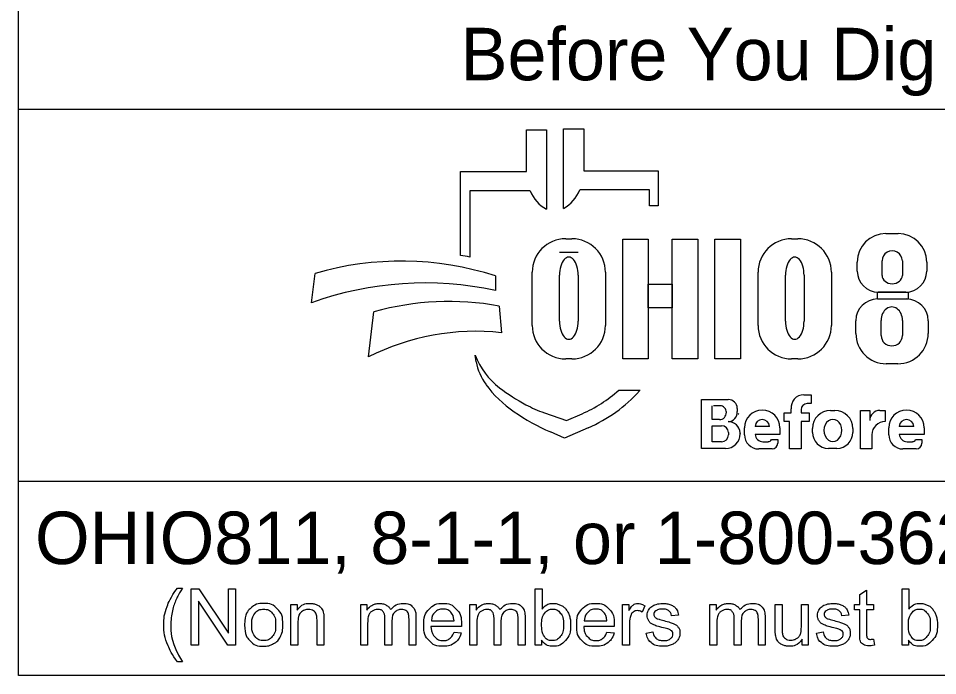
# Model space of a CAD drawing. Extents: x 0 to 34, y 0 to 22.
# Drawn here: x 2.978 to 5.431, y 2.143 to 3.897 of the extents above; entities that cross this region are included whole.
import ezdxf

# ---------------------------------------------------------------- set-up
doc = ezdxf.new("R2010")
doc.units = 0
doc.layers.add('GM_X_Adjacent_County', color=7, linetype='Continuous')
doc.layers.add('GM_X_Township', color=7, linetype='Continuous')

msp = doc.modelspace()

# ---------------------------------------------------------------- linework, layer by layer
at = {"layer": 'GM_X_Adjacent_County'}
for p, q in [((4.3335, 3.4883), (4.3335, 3.5998)), ((4.3335, 3.5998), (4.3872, 3.5998)), ((4.3872, 3.5998), (4.3872, 3.3877)), ((4.4329, 3.39), (4.4329, 3.6021)), ((4.4329, 3.6021), (4.4865, 3.6021)), ((4.4865, 3.6021), (4.4865, 3.4906)), ((4.1576, 3.2644), (4.1576, 3.4883)), ((4.1576, 3.4883), (4.3335, 3.4883)), ((4.4865, 3.4906), (4.6857, 3.4906)), ((4.6857, 3.4906), (4.6857, 3.3968)), ((4.1828, 3.4369), (4.1828, 3.26)), ((4.3439, 3.4369), (4.1828, 3.4369)), ((4.6625, 3.4392), (4.4761, 3.4392)), ((4.6625, 3.3968), (4.6625, 3.4392)), ((4.6857, 3.3968), (4.6625, 3.3968)), ((5.2931, 3.3231), (5.3258, 3.3231)), ((4.4385, 3.3091), (4.4551, 3.3091)), ((5.0416, 3.3091), (5.0581, 3.3091)), ((4.4718, 3.2721), (4.422, 3.2721)), ((5.2168, 3.2225), (5.2168, 3.2468)), ((5.283, 3.2111), (5.283, 3.2504)), ((5.3371, 3.2504), (5.3371, 3.2111)), ((5.4022, 3.2468), (5.4022, 3.2225)), ((3.7602, 3.1381), (3.7696, 3.2162)), ((4.3491, 3.0776), (4.3491, 3.2196)), ((4.5445, 3.2196), (4.5445, 3.0776)), ((4.9521, 3.0776), (4.9521, 3.2196)), ((5.1476, 3.2196), (5.1476, 3.0776)), ((4.2509, 3.2097), (4.2509, 3.1709)), ((4.422, 3.089), (4.422, 3.2114)), ((4.4718, 3.2114), (4.4718, 3.089)), ((5.025, 3.089), (5.025, 3.2114)), ((5.0748, 3.2114), (5.0748, 3.089)), ((5.3462, 3.1665), (5.2728, 3.1665)), ((5.271, 3.1482), (5.3483, 3.1482)), ((4.2608, 3.1291), (4.2671, 3.0582)), ((3.912, 2.9936), (3.9267, 3.1137)), ((5.2131, 3.0563), (5.2131, 3.0903)), ((5.2806, 3.0503), (5.2806, 3.0912)), ((5.3374, 3.0912), (5.3374, 3.0503)), ((5.4062, 3.0903), (5.4062, 3.0563)), ((4.1997, 2.9807), (4.1967, 2.9986)), ((4.4551, 2.9882), (4.4385, 2.9882)), ((5.0581, 2.9882), (5.0416, 2.9882)), ((5.3252, 2.9753), (5.2941, 2.9753)), ((4.58, 2.9048), (4.6375, 2.9048)), ((4.8013, 2.749), (4.8013, 2.8798)), ((4.8013, 2.8798), (4.8725, 2.8798)), ((5.0739, 2.8926), (5.0934, 2.8926)), ((5.0934, 2.8926), (5.0934, 2.8696)), ((4.8293, 2.8263), (4.8293, 2.8632)), ((4.8545, 2.8632), (4.8332, 2.8632)), ((4.8963, 2.856), (4.8963, 2.8481)), ((5.0406, 2.8442), (5.0406, 2.8546)), ((5.0667, 2.8526), (5.0667, 2.8442)), ((5.0934, 2.8691), (5.0832, 2.8691)), ((5.1451, 2.8508), (5.1573, 2.8508)), ((5.2254, 2.7478), (5.2254, 2.8505)), ((5.2254, 2.8505), (5.2499, 2.8505)), ((5.2499, 2.8505), (5.2499, 2.8237)), ((5.2772, 2.8505), (5.291, 2.8505)), ((5.291, 2.8505), (5.291, 2.8209)), ((4.3816, 2.8444), (4.441, 2.8239)), ((4.441, 2.8239), (4.4821, 2.8417)), ((4.8487, 2.8263), (4.8293, 2.8263)), ((5.0213, 2.8212), (5.0213, 2.8442)), ((5.0213, 2.8442), (5.0406, 2.8442)), ((5.0667, 2.8442), (5.0883, 2.8442)), ((5.0883, 2.8442), (5.0883, 2.8212)), ((4.4983, 2.8044), (4.435, 2.7769)), ((4.8293, 2.7669), (4.8293, 2.8097)), ((4.8293, 2.8097), (4.8548, 2.8097)), ((4.9159, 2.7858), (4.9159, 2.8042)), ((4.9824, 2.8082), (4.9439, 2.8082)), ((5.0104, 2.8042), (5.0104, 2.7866)), ((5.0362, 2.8212), (5.0213, 2.8212)), ((5.0362, 2.7478), (5.0362, 2.8212)), ((5.0883, 2.8212), (5.0667, 2.8212)), ((5.0667, 2.8212), (5.0667, 2.7478)), ((5.0973, 2.7922), (5.0973, 2.8029)), ((5.2051, 2.8029), (5.2051, 2.7922)), ((5.3008, 2.7858), (5.3008, 2.8042)), ((5.3674, 2.8082), (5.3288, 2.8082)), ((5.3953, 2.8042), (5.3953, 2.7866)), ((4.435, 2.7769), (4.3976, 2.7934)), ((4.8729, 2.7916), (4.8729, 2.7853)), ((4.9043, 2.7887), (4.9043, 2.7884)), ((5.0104, 2.7866), (4.944, 2.7866)), ((4.9876, 2.7729), (5.0045, 2.7729)), ((5.0045, 2.7729), (5.0045, 2.7631)), ((5.2559, 2.786), (5.2559, 2.7478)), ((5.3953, 2.7866), (5.3289, 2.7866)), ((5.3725, 2.7729), (5.3894, 2.7729)), ((5.3894, 2.7729), (5.3894, 2.7631)), ((4.865, 2.749), (4.8013, 2.749)), ((4.8546, 2.7669), (4.8293, 2.7669)), ((4.9649, 2.7673), (4.979, 2.7673)), ((5.1623, 2.7494), (5.1401, 2.7494)), ((5.3498, 2.7673), (5.3639, 2.7673)), ((4.9892, 2.7478), (4.9538, 2.7478)), ((5.0667, 2.7478), (5.0362, 2.7478)), ((5.2559, 2.7478), (5.2254, 2.7478)), ((5.3742, 2.7478), (5.3388, 2.7478))]:
    msp.add_line(p, q, dxfattribs=at)
for points in [[(4.591, 3.3081), (4.6589, 3.3081), (4.6589, 2.9881), (4.591, 2.9881)], [(4.7231, 3.3081), (4.7911, 3.3081), (4.7911, 2.9881), (4.7231, 2.9881)], [(4.8364, 3.3081), (4.9052, 3.3081), (4.9052, 2.9881), (4.8364, 2.9881)], [(4.6589, 3.1882), (4.7231, 3.1882), (4.7231, 3.1242), (4.6589, 3.1242)], [(5.2706, 3.1665), (5.3523, 3.1665), (5.3523, 3.1481), (5.2706, 3.1481)]]:
    msp.add_lwpolyline(points, close=True, dxfattribs=at)
for points in [[(3.4021, 2.3766), (3.4153, 2.3766)], [(3.4389, 2.2239), (3.4389, 2.3741), (3.4592, 2.3741), (3.5382, 2.2561), (3.5382, 2.3741), (3.5572, 2.3741), (3.5572, 2.2239), (3.5369, 2.2239), (3.4579, 2.3419), (3.4579, 2.2239), (3.4389, 2.2239)], [(4.3743, 2.2239), (4.3573, 2.2239), (4.3573, 2.3741), (4.3757, 2.3741), (4.3757, 2.3206)], [(5.2233, 2.2558), (5.2233, 2.3185), (5.2097, 2.3185), (5.2097, 2.3328), (5.2233, 2.3328), (5.2233, 2.3597), (5.2417, 2.3708), (5.2417, 2.3328), (5.2601, 2.3328), (5.2601, 2.3185), (5.2417, 2.3185), (5.2417, 2.2547)], [(5.3534, 2.2239), (5.3363, 2.2239), (5.3363, 2.3741), (5.3548, 2.3741), (5.3548, 2.3206)], [(3.7048, 2.2239), (3.7048, 2.3328), (3.7214, 2.3328), (3.7214, 2.3173)], [(3.8912, 2.2239), (3.8912, 2.3328), (3.9077, 2.3328), (3.9077, 2.3174)], [(4.1826, 2.2239), (4.1826, 2.3328), (4.1991, 2.3328), (4.1991, 2.3174)], [(4.5904, 2.2239), (4.5904, 2.3328), (4.607, 2.3328), (4.607, 2.3163)], [(4.8236, 2.2239), (4.8236, 2.3328), (4.8401, 2.3328), (4.8401, 2.3174)], [(4.9979, 2.2654), (4.9979, 2.3328), (5.0164, 2.3328), (5.0164, 2.2724)], [(5.0676, 2.2745), (5.0676, 2.3328), (5.0861, 2.3328), (5.0861, 2.2239), (5.0696, 2.2239)], [(4.6495, 2.3293), (4.643, 2.3122)], [(3.7233, 2.2833), (3.7233, 2.2239), (3.7048, 2.2239)], [(3.7932, 2.2908), (3.7932, 2.2239), (3.7748, 2.2239), (3.7748, 2.2901)], [(3.9743, 2.2871), (3.9743, 2.2239), (3.9559, 2.2239), (3.9559, 2.2946)], [(4.0388, 2.2986), (4.0388, 2.2239), (4.0203, 2.2239), (4.0203, 2.2924)], [(4.0799, 2.2887), (4.1406, 2.2887)], [(4.2657, 2.2871), (4.2657, 2.2239), (4.2473, 2.2239), (4.2473, 2.2946)], [(4.3301, 2.2986), (4.3301, 2.2239), (4.3117, 2.2239), (4.3117, 2.2924)], [(4.4879, 2.2887), (4.5486, 2.2887)], [(4.7394, 2.3046), (4.7213, 2.3022)], [(4.9067, 2.2871), (4.9067, 2.2239), (4.8883, 2.2239), (4.8883, 2.2946)], [(4.9711, 2.2986), (4.9711, 2.2239), (4.9527, 2.2239), (4.9527, 2.2924)], [(5.194, 2.3046), (5.1759, 2.3022)], [(3.9097, 2.2803), (3.9097, 2.2239), (3.8912, 2.2239)], [(4.16, 2.2736), (4.0788, 2.2736)], [(4.1404, 2.2591), (4.1595, 2.2567)], [(4.201, 2.2803), (4.201, 2.2239), (4.1826, 2.2239)], [(4.568, 2.2736), (4.4868, 2.2736)], [(4.5484, 2.2591), (4.5675, 2.2567)], [(4.6088, 2.2809), (4.6088, 2.2239), (4.5904, 2.2239)], [(4.653, 2.2564), (4.6712, 2.2593)], [(4.842, 2.2803), (4.842, 2.2239), (4.8236, 2.2239)], [(5.1076, 2.2564), (5.1258, 2.2593)], [(4.3743, 2.2375), (4.3743, 2.2239)], [(5.0696, 2.2239), (5.0696, 2.24)], [(5.2601, 2.2404), (5.2628, 2.2241)], [(5.3534, 2.2375), (5.3534, 2.2239)], [(3.4153, 2.1798), (3.4021, 2.1798)]]:
    msp.add_lwpolyline(points, dxfattribs=at)
for centre, radius, start, end in [((4.4353, 3.4736), 0.0985, 201.9296, 240.7469), ((4.3847, 3.476), 0.0985, 299.2531, 338.0704), ((5.2931, 3.2468), 0.0763, 90, 180), ((5.3258, 3.2468), 0.0763, 0, 90), ((4.4385, 3.2196), 0.0895, 90, 180), ((4.4551, 3.2196), 0.0895, 0, 90), ((5.0416, 3.2196), 0.0895, 90, 180), ((5.0581, 3.2196), 0.0895, 0, 90), ((4.0295, 2.4554), 0.8191, 79.2074, 81.0007), ((3.9997, 2.4302), 0.8191, 72.1402, 106.3144), ((5.2728, 3.2225), 0.056, 180, 270), ((5.3462, 3.2225), 0.056, 270, 0), ((4.0628, 2.2991), 0.8919, 77.8238, 109.8274), ((4.1267, 2.4094), 0.7322, 79.44, 105.8467), ((5.271, 3.0903), 0.0579, 90, 180), ((5.3483, 3.0903), 0.0579, 0, 90), ((4.4385, 3.0776), 0.0895, 180, 270), ((4.4551, 3.0776), 0.0895, 270, 0), ((5.0416, 3.0776), 0.0895, 180, 270), ((5.0581, 3.0776), 0.0895, 270, 0), ((4.1987, 2.4262), 0.6357, 83.8248, 116.8021), ((5.2941, 3.0563), 0.081, 180, 270), ((5.3252, 3.0563), 0.081, 270, 0), ((4.3841, 3.0707), 0.2008, 201.0457, 232.5314), ((4.341, 3.0048), 0.1433, 189.6817, 216.0884), ((4.4747, 3.1022), 0.3088, 216.0884, 235.7167), ((4.5766, 3.3219), 0.5173, 232.5314, 241.794), ((4.3387, 3.1722), 0.3602, 293.4582, 312.0712), ((4.3387, 3.1722), 0.401, 293.4582, 317.8286), ((4.8725, 2.856), 0.0238, 0, 90), ((5.0739, 2.859), 0.0335, 90, 187.5187), ((4.6412, 3.3465), 0.6044, 235.7167, 246.2325), ((4.4914, 3.1631), 0.3371, 241.794, 250.9821), ((4.8505, 2.8463), 0.0169, 357.8325, 90), ((4.8721, 2.8453), 0.0243, 270, 6.6529), ((4.9631, 2.8042), 0.0473, 0, 180), ((5.0832, 2.8526), 0.0165, 90, 180), ((5.1451, 2.8029), 0.0478, 90, 180), ((5.1573, 2.8029), 0.0478, 0, 90), ((5.2768, 2.8237), 0.0269, 89.2449, 180), ((5.3481, 2.8042), 0.0473, 0, 180), ((4.8487, 2.845), 0.0187, 270, 2.0582), ((4.8827, 2.8438), 0.0175, 347.4023, 0), ((4.9632, 2.8072), 0.0193, 2.9632, 177.0368), ((5.3481, 2.8072), 0.0193, 2.9632, 177.0368), ((4.8548, 2.7916), 0.0181, 0, 90), ((4.8722, 2.7889), 0.0321, 4.0748, 90), ((5.2908, 2.786), 0.0349, 89.6033, 180), ((4.8546, 2.7853), 0.0184, 270, 0), ((4.865, 2.7884), 0.0393, 270, 0), ((4.8714, 2.7887), 0.033, 0, 11.7502), ((4.9538, 2.7858), 0.038, 180, 270), ((4.9649, 2.7883), 0.021, 184.827, 270), ((4.979, 2.7767), 0.00938, 270, 335.9979), ((5.1401, 2.7922), 0.0428, 180, 270), ((5.1623, 2.7922), 0.0428, 270, 0), ((5.3388, 2.7858), 0.038, 180, 270), ((5.3498, 2.7883), 0.021, 184.827, 270), ((5.3639, 2.7767), 0.00938, 270, 335.9979), ((4.9892, 2.7631), 0.0152, 270, 0), ((5.3742, 2.7631), 0.0152, 270, 0)]:
    msp.add_arc(centre, radius, start, end, dxfattribs=at)
for centre, major_axis, ratio, start_param, end_param in [((5.31, 3.2504), (0.0271, 0), 0.969373, 0, 3.141593), ((4.4469, 3.2114), (0, 0.0484), 0.514403, 4.712389, 7.853982), ((5.0499, 3.2114), (0, 0.0484), 0.514403, 4.712389, 7.853982), ((5.31, 3.2111), (0.0271, 0), 0.818453, 3.141593, 6.283185), ((5.309, 3.0912), (0, 0.0358), 0.794529, 4.712389, 7.853982), ((4.4469, 3.089), (0, 0.0484), 0.514403, 1.570796, 4.712389), ((5.0499, 3.089), (0, 0.0484), 0.514403, 1.570796, 4.712389), ((5.309, 3.0503), (0.0284, 0), 0.959837, 3.141593, 6.283185), ((5.1517, 2.7976), (0, 0.029), 0.832186, 4.712389, 7.853982), ((5.1517, 2.7976), (0, 0.0302), 0.797287, 1.570796, 4.712389)]:
    msp.add_ellipse(centre, major_axis=major_axis, ratio=ratio, start_param=start_param, end_param=end_param, dxfattribs=at)
for points in [[(3.4021, 2.1798), (3.3869, 2.199), (3.3763, 2.2248), (3.3657, 2.2506), (3.3657, 2.2783), (3.3657, 2.3026), (3.3736, 2.325), (3.3829, 2.3509), (3.4021, 2.3766)], [(3.4153, 2.3766), (3.4029, 2.3553), (3.3989, 2.3462), (3.3927, 2.332), (3.3891, 2.3167), (3.3847, 2.2975), (3.3847, 2.2782), (3.3847, 2.2289), (3.4153, 2.1798)], [(3.5814, 2.2783), (3.5814, 2.3085), (3.5981, 2.3231), (3.6122, 2.3352), (3.6323, 2.3352), (3.6547, 2.3352), (3.669, 2.3205), (3.6832, 2.3058), (3.6832, 2.2799), (3.6832, 2.2589), (3.6769, 2.2469), (3.6706, 2.2348), (3.6586, 2.2282), (3.6466, 2.2215), (3.6323, 2.2215), (3.6095, 2.2215), (3.5954, 2.2362), (3.5814, 2.2508), (3.5814, 2.2783)], [(3.7214, 2.3173), (3.7334, 2.3352), (3.756, 2.3352), (3.7659, 2.3352), (3.7741, 2.3316), (3.7823, 2.3281), (3.7864, 2.3224), (3.7905, 2.3166), (3.7922, 2.3087), (3.7932, 2.3036), (3.7932, 2.2908)], [(3.9077, 2.3174), (3.9128, 2.3254), (3.9214, 2.3303), (3.9299, 2.3352), (3.9407, 2.3352), (3.9528, 2.3352), (3.9606, 2.3301), (3.9683, 2.3251), (3.9715, 2.3161), (3.9844, 2.3352), (4.0051, 2.3352), (4.0213, 2.3352), (4.03, 2.3262), (4.0388, 2.3172), (4.0388, 2.2986)], [(4.1595, 2.2567), (4.155, 2.24), (4.1428, 2.2307), (4.1306, 2.2215), (4.1117, 2.2215), (4.0878, 2.2215), (4.0738, 2.2362), (4.0598, 2.2509), (4.0598, 2.2774), (4.0598, 2.3049), (4.074, 2.32), (4.0881, 2.3352), (4.1106, 2.3352), (4.1324, 2.3352), (4.1463, 2.3203), (4.1601, 2.3055), (4.1601, 2.2785), (4.1601, 2.2769), (4.16, 2.2736)], [(4.1991, 2.3174), (4.2042, 2.3254), (4.2127, 2.3303), (4.2212, 2.3352), (4.2321, 2.3352), (4.2442, 2.3352), (4.2519, 2.3301), (4.2597, 2.3251), (4.2628, 2.3161), (4.2758, 2.3352), (4.2965, 2.3352), (4.3127, 2.3352), (4.3214, 2.3262), (4.3301, 2.3172), (4.3301, 2.2986)], [(4.3757, 2.3206), (4.3874, 2.3352), (4.4055, 2.3352), (4.4155, 2.3352), (4.4245, 2.3311), (4.4335, 2.3271), (4.4392, 2.3198), (4.445, 2.3124), (4.4483, 2.3021), (4.4516, 2.2918), (4.4516, 2.28), (4.4516, 2.252), (4.4378, 2.2368), (4.4239, 2.2215), (4.4046, 2.2215), (4.3853, 2.2215), (4.3743, 2.2375)], [(4.5675, 2.2567), (4.563, 2.24), (4.5508, 2.2307), (4.5386, 2.2215), (4.5196, 2.2215), (4.4958, 2.2215), (4.4818, 2.2362), (4.4678, 2.2509), (4.4678, 2.2774), (4.4678, 2.3049), (4.482, 2.32), (4.4961, 2.3352), (4.5186, 2.3352), (4.5404, 2.3352), (4.5543, 2.3203), (4.5681, 2.3055), (4.5681, 2.2785), (4.5681, 2.2769), (4.568, 2.2736)], [(4.607, 2.3163), (4.6133, 2.3278), (4.6187, 2.3315), (4.6241, 2.3352), (4.6305, 2.3352), (4.6398, 2.3352), (4.6495, 2.3293)], [(4.6712, 2.2593), (4.6727, 2.2483), (4.6798, 2.2425), (4.6868, 2.2366), (4.6995, 2.2366), (4.7122, 2.2366), (4.7184, 2.2418), (4.7245, 2.247), (4.7245, 2.254), (4.7245, 2.2602), (4.7191, 2.2638), (4.7153, 2.2663), (4.7002, 2.2701), (4.6799, 2.2752), (4.672, 2.2789), (4.6642, 2.2827), (4.6601, 2.2893), (4.6561, 2.2959), (4.6561, 2.3038), (4.6561, 2.3111), (4.6594, 2.3173), (4.6628, 2.3235), (4.6685, 2.3276), (4.6728, 2.3308), (4.6803, 2.333), (4.6877, 2.3352), (4.6962, 2.3352), (4.709, 2.3352), (4.7187, 2.3315), (4.7284, 2.3278), (4.733, 2.3215), (4.7377, 2.3152), (4.7394, 2.3046)], [(4.8401, 2.3174), (4.8452, 2.3254), (4.8537, 2.3303), (4.8622, 2.3352), (4.8731, 2.3352), (4.8852, 2.3352), (4.8929, 2.3301), (4.9007, 2.3251), (4.9038, 2.3161), (4.9168, 2.3352), (4.9375, 2.3352), (4.9537, 2.3352), (4.9624, 2.3262), (4.9711, 2.3172), (4.9711, 2.2986)], [(5.1258, 2.2593), (5.1273, 2.2483), (5.1343, 2.2425), (5.1414, 2.2366), (5.154, 2.2366), (5.1668, 2.2366), (5.1729, 2.2418), (5.1791, 2.247), (5.1791, 2.254), (5.1791, 2.2602), (5.1736, 2.2638), (5.1698, 2.2663), (5.1548, 2.2701), (5.1345, 2.2752), (5.1266, 2.2789), (5.1188, 2.2827), (5.1147, 2.2893), (5.1107, 2.2959), (5.1107, 2.3038), (5.1107, 2.3111), (5.114, 2.3173), (5.1173, 2.3235), (5.1231, 2.3276), (5.1274, 2.3308), (5.1348, 2.333), (5.1423, 2.3352), (5.1508, 2.3352), (5.1636, 2.3352), (5.1733, 2.3315), (5.183, 2.3278), (5.1876, 2.3215), (5.1922, 2.3152), (5.194, 2.3046)], [(5.3548, 2.3206), (5.3664, 2.3352), (5.3846, 2.3352), (5.3946, 2.3352), (5.4036, 2.3311), (5.4125, 2.3271), (5.4183, 2.3198), (5.4241, 2.3124), (5.4274, 2.3021), (5.4306, 2.2918), (5.4306, 2.28), (5.4306, 2.252), (5.4168, 2.2368), (5.403, 2.2215), (5.3836, 2.2215), (5.3644, 2.2215), (5.3534, 2.2375)], [(3.6003, 2.2783), (3.6003, 2.2574), (3.6094, 2.247), (3.6185, 2.2366), (3.6323, 2.2366), (3.646, 2.2366), (3.6551, 2.2471), (3.6642, 2.2575), (3.6642, 2.279), (3.6642, 2.2991), (3.6551, 2.3095), (3.6459, 2.3199), (3.6323, 2.3199), (3.6185, 2.3199), (3.6094, 2.3096), (3.6003, 2.2992), (3.6003, 2.2783)], [(3.7748, 2.2901), (3.7748, 2.3013), (3.7726, 2.3069), (3.7705, 2.3125), (3.765, 2.3158), (3.7595, 2.3191), (3.7521, 2.3191), (3.7404, 2.3191), (3.7318, 2.3117), (3.7233, 2.3042), (3.7233, 2.2833)], [(3.9559, 2.2946), (3.9559, 2.3069), (3.9514, 2.313), (3.9469, 2.3191), (3.9366, 2.3191), (3.9288, 2.3191), (3.9222, 2.315), (3.9156, 2.311), (3.9126, 2.3031), (3.9097, 2.2952), (3.9097, 2.2803)], [(4.0203, 2.2924), (4.0203, 2.3035), (4.0185, 2.3083), (4.0168, 2.3132), (4.012, 2.3162), (4.0073, 2.3191), (4.001, 2.3191), (3.9895, 2.3191), (3.9819, 2.3115), (3.9743, 2.3039), (3.9743, 2.2871)], [(4.1406, 2.2887), (4.1394, 2.3025), (4.1337, 2.3094), (4.1249, 2.3201), (4.1108, 2.3201), (4.0981, 2.3201), (4.0894, 2.3115), (4.0808, 2.303), (4.0799, 2.2887)], [(4.2473, 2.2946), (4.2473, 2.3069), (4.2428, 2.313), (4.2383, 2.3191), (4.228, 2.3191), (4.2202, 2.3191), (4.2136, 2.315), (4.207, 2.311), (4.204, 2.3031), (4.201, 2.2952), (4.201, 2.2803)], [(4.3117, 2.2924), (4.3117, 2.3035), (4.3099, 2.3083), (4.3081, 2.3132), (4.3034, 2.3162), (4.2987, 2.3191), (4.2923, 2.3191), (4.2809, 2.3191), (4.2733, 2.3115), (4.2657, 2.3039), (4.2657, 2.2871)], [(4.3741, 2.2792), (4.3741, 2.2596), (4.3794, 2.2509), (4.3881, 2.2366), (4.4029, 2.2366), (4.415, 2.2366), (4.4238, 2.2471), (4.4326, 2.2576), (4.4326, 2.2784), (4.4326, 2.2998), (4.4241, 2.3099), (4.4157, 2.3201), (4.4038, 2.3201), (4.3917, 2.3201), (4.3829, 2.3096), (4.3741, 2.299), (4.3741, 2.2792)], [(4.5486, 2.2887), (4.5474, 2.3025), (4.5417, 2.3094), (4.5328, 2.3201), (4.5188, 2.3201), (4.5061, 2.3201), (4.4974, 2.3115), (4.4888, 2.303), (4.4879, 2.2887)], [(4.643, 2.3122), (4.6363, 2.3162), (4.6295, 2.3162), (4.6235, 2.3162), (4.6187, 2.3125), (4.6139, 2.3089), (4.6119, 2.3024), (4.6088, 2.2926), (4.6088, 2.2809)], [(4.7213, 2.3022), (4.7201, 2.3106), (4.7142, 2.3153), (4.7083, 2.3201), (4.6975, 2.3201), (4.6848, 2.3201), (4.6794, 2.3159), (4.6739, 2.3116), (4.6739, 2.306), (4.6739, 2.3024), (4.6762, 2.2995), (4.6785, 2.2966), (4.6833, 2.2946), (4.686, 2.2936), (4.6996, 2.2899), (4.7192, 2.2847), (4.7269, 2.2813), (4.7347, 2.278), (4.7391, 2.2717), (4.7435, 2.2653), (4.7435, 2.2559), (4.7435, 2.2467), (4.7381, 2.2386), (4.7327, 2.2304), (4.7226, 2.226), (4.7124, 2.2215), (4.6996, 2.2215), (4.6784, 2.2215), (4.6672, 2.2303), (4.6561, 2.2391), (4.653, 2.2564)], [(4.8883, 2.2946), (4.8883, 2.3069), (4.8838, 2.313), (4.8793, 2.3191), (4.869, 2.3191), (4.8612, 2.3191), (4.8546, 2.315), (4.848, 2.311), (4.845, 2.3031), (4.842, 2.2952), (4.842, 2.2803)], [(4.9527, 2.2924), (4.9527, 2.3035), (4.9509, 2.3083), (4.9491, 2.3132), (4.9444, 2.3162), (4.9397, 2.3191), (4.9333, 2.3191), (4.9219, 2.3191), (4.9143, 2.3115), (4.9067, 2.3039), (4.9067, 2.2871)], [(5.1759, 2.3022), (5.1747, 2.3106), (5.1688, 2.3153), (5.1629, 2.3201), (5.1521, 2.3201), (5.1394, 2.3201), (5.1339, 2.3159), (5.1285, 2.3116), (5.1285, 2.306), (5.1285, 2.3024), (5.1308, 2.2995), (5.133, 2.2966), (5.1378, 2.2946), (5.1406, 2.2936), (5.1542, 2.2899), (5.1737, 2.2847), (5.1815, 2.2813), (5.1893, 2.278), (5.1937, 2.2717), (5.1981, 2.2653), (5.1981, 2.2559), (5.1981, 2.2467), (5.1927, 2.2386), (5.1873, 2.2304), (5.1772, 2.226), (5.167, 2.2215), (5.1542, 2.2215), (5.1329, 2.2215), (5.1218, 2.2303), (5.1107, 2.2391), (5.1076, 2.2564)], [(5.3532, 2.2792), (5.3532, 2.2596), (5.3585, 2.2509), (5.3672, 2.2366), (5.382, 2.2366), (5.3941, 2.2366), (5.4029, 2.2471), (5.4116, 2.2576), (5.4116, 2.2784), (5.4116, 2.2998), (5.4032, 2.3099), (5.3948, 2.3201), (5.3828, 2.3201), (5.3708, 2.3201), (5.362, 2.3096), (5.3532, 2.299), (5.3532, 2.2792)], [(4.0788, 2.2736), (4.0799, 2.2557), (4.089, 2.2462), (4.0981, 2.2366), (4.1117, 2.2366), (4.1219, 2.2366), (4.1291, 2.242), (4.1362, 2.2473), (4.1404, 2.2591)], [(4.4868, 2.2736), (4.4879, 2.2557), (4.497, 2.2462), (4.5061, 2.2366), (4.5197, 2.2366), (4.5299, 2.2366), (4.537, 2.242), (4.5442, 2.2473), (4.5484, 2.2591)], [(5.0696, 2.24), (5.0569, 2.2215), (5.0351, 2.2215), (5.0255, 2.2215), (5.0171, 2.2252), (5.0088, 2.2289), (5.0047, 2.2345), (5.0007, 2.2401), (4.9991, 2.2482), (4.9979, 2.2536), (4.9979, 2.2654)], [(5.0164, 2.2724), (5.0164, 2.258), (5.0175, 2.253), (5.0192, 2.2457), (5.0249, 2.2416), (5.0305, 2.2374), (5.0388, 2.2374), (5.0471, 2.2374), (5.0543, 2.2417), (5.0616, 2.2459), (5.0646, 2.2533), (5.0676, 2.2606), (5.0676, 2.2745)], [(5.2628, 2.2241), (5.255, 2.2224), (5.2488, 2.2224), (5.2388, 2.2224), (5.2333, 2.2256), (5.2278, 2.2288), (5.2255, 2.234), (5.2233, 2.2392), (5.2233, 2.2558)], [(5.2417, 2.2547), (5.2417, 2.2468), (5.2427, 2.2445), (5.2436, 2.2423), (5.2458, 2.2409), (5.248, 2.2396), (5.2521, 2.2396), (5.2551, 2.2396), (5.2601, 2.2404)]]:
    msp.add_open_spline(points, degree=3, dxfattribs=at)
at = {"layer": 'GM_X_Township'}
for p, q in [((2.9775, 2.1428), (2.9775, 4.4803)), ((2.9775, 3.6553), (7.2275, 3.6553)), ((7.2275, 2.6607), (2.9775, 2.6607)), ((7.2275, 2.1428), (2.9775, 2.1428))]:
    msp.add_line(p, q, dxfattribs=at)

# ---------------------------------------------------------------- texts
at = {"layer": 'GM_X_Adjacent_County'}
for s, p in [('Before You Dig', (4.1583, 3.7321)), ('OHIO811, 8-1-1, or 1-800-362-2764', (3.022, 2.4406))]:
    msp.add_text(s, height=0.14, dxfattribs=at).set_placement(p)

doc.saveas('drawing.dxf')
